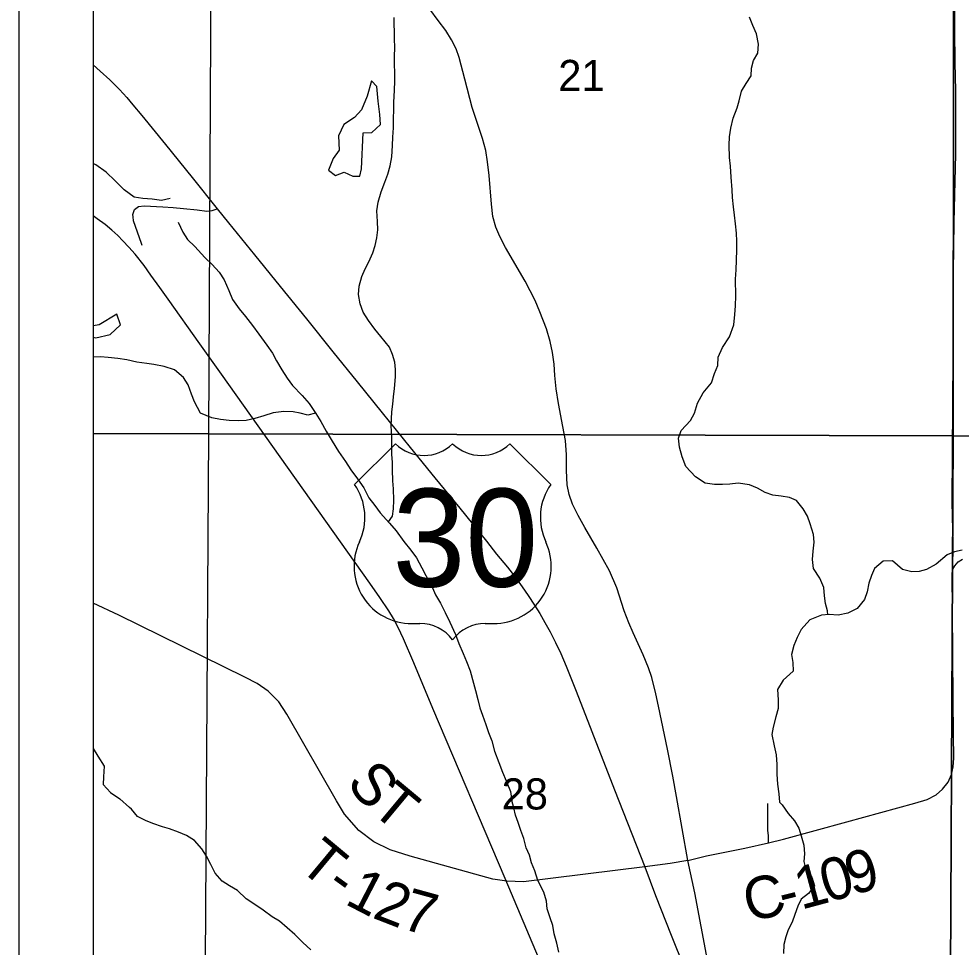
# Model space of a CAD drawing. Extents: x 0 to 34, y 0 to 22.
# Drawn here: x 2 to 3.267, y 18.298 to 19.546 of the extents above; entities that cross this region are included whole.
import ezdxf

# ---------------------------------------------------------------- set-up
doc = ezdxf.new("R2010")
doc.units = 0
for name, color, linetype in [('Default', 7, 'Continuous'), ('SH_Cut_Line', 7, 'Continuous'), ('SH_Data', 7, 'Continuous')]:
    doc.layers.add(name, color=color, linetype=linetype)

msp = doc.modelspace()

# ---------------------------------------------------------------- linework, layer by layer
at = {"layer": 'Default'}
for p, q in [((2.5064, 18.9747), (2.4515, 18.9198)), ((2.7152, 18.9198), (2.6602, 18.9747)), ((2.5284, 18.733), (2.5394, 18.733)), ((2.6273, 18.733), (2.6383, 18.733))]:
    msp.add_line(p, q, dxfattribs=at)
for points in [[(2.1, 20.9), (2.1, 17.0156)], [(3.2565, 19.9852), (3.2557, 19.9639), (3.2561, 19.9392), (3.2581, 19.9016), (3.2594, 19.8699), (3.2596, 19.8254), (3.2589, 19.7384), (3.2581, 19.6526), (3.258, 19.5305), (3.2588, 19.4869), (3.2597, 19.4497), (3.2597, 19.3639), (3.2575, 19.2725), (3.2561, 19.1717), (3.2558, 19.0924), (3.2548, 18.8963), (3.2559, 18.8401), (3.2557, 18.8052)], [(2.8997, 18.4145), (2.8844, 18.5005), (2.8795, 18.5277), (2.8723, 18.5641), (2.8604, 18.6218), (2.8567, 18.6382), (2.8511, 18.6602), (2.8468, 18.6732), (2.8396, 18.691), (2.8259, 18.7204), (2.8202, 18.734), (2.8142, 18.75), (2.8042, 18.781), (2.7941, 18.8036), (2.7774, 18.8343), (2.7611, 18.8621), (2.752, 18.8784), (2.7445, 18.8934), (2.7401, 18.9063), (2.7374, 18.9195), (2.7366, 18.9387), (2.7363, 18.9597), (2.735, 18.979), (2.7317, 18.9978), (2.7255, 19.0289), (2.7224, 19.0487), (2.7207, 19.0666), (2.7198, 19.0818), (2.7177, 19.0976), (2.7147, 19.1124), (2.7097, 19.1293), (2.7007, 19.152), (2.6941, 19.1673), (2.6809, 19.1935), (2.6545, 19.2386), (2.6467, 19.2536), (2.6415, 19.2661), (2.6376, 19.2802), (2.6356, 19.2968), (2.6323, 19.3356), (2.6303, 19.3537), (2.6278, 19.3692), (2.6234, 19.385), (2.6095, 19.4267), (2.5996, 19.465), (2.5919, 19.4941), (2.5881, 19.5059), (2.582, 19.518), (2.5742, 19.5302), (2.5639, 19.5437), (2.5525, 19.5592)], [(2.4971, 18.8696), (2.5026, 18.8771), (2.504, 18.8874), (2.5042, 18.8988), (2.5036, 18.914), (2.5031, 18.925), (2.5025, 18.9394), (2.5023, 18.95), (2.5014, 18.9603), (2.5017, 18.9709), (2.5015, 18.9846), (2.5009, 18.9987), (2.5011, 19.0082), (2.5018, 19.0177), (2.5028, 19.0279), (2.5038, 19.0378), (2.5051, 19.0492), (2.5064, 19.0648), (2.5067, 19.0747), (2.5054, 19.0846), (2.5026, 19.0948), (2.4983, 19.1046), (2.4867, 19.1189), (2.4786, 19.1286), (2.4701, 19.1403), (2.4631, 19.1516), (2.4588, 19.1629), (2.4567, 19.1754), (2.4577, 19.1865), (2.4613, 19.1994), (2.4657, 19.2098), (2.4705, 19.2193), (2.476, 19.2316), (2.4793, 19.2415), (2.4814, 19.2518), (2.4828, 19.2624), (2.4823, 19.2735), (2.4813, 19.2879), (2.483, 19.2997), (2.4874, 19.3134), (2.4921, 19.3264), (2.4962, 19.3371), (2.4994, 19.3485), (2.5015, 19.3607), (2.5025, 19.3756), (2.5031, 19.387), (2.5036, 19.3995), (2.5038, 19.4124), (2.5041, 19.4231), (2.5043, 19.4341), (2.5052, 19.4497), (2.5058, 19.4626), (2.5053, 19.4957), (2.5056, 19.5071), (2.505, 19.5196), (2.5046, 19.5477)], [(3.0879, 18.7448), (3.0876, 18.7502), (3.0848, 18.7601), (3.0835, 18.7703), (3.0826, 18.7813), (3.0771, 18.7938), (3.0686, 18.8069), (3.0673, 18.8191), (3.0683, 18.8301), (3.0696, 18.8423), (3.0687, 18.8525), (3.0643, 18.8669), (3.0604, 18.8775), (3.0546, 18.8873), (3.0457, 18.8982), (3.0362, 18.9026), (3.0252, 18.904), (3.0138, 18.9057), (3.0038, 18.9093), (2.9931, 18.9149), (2.9825, 18.9193), (2.9673, 18.9217), (2.9563, 18.9204), (2.9464, 18.9199), (2.9354, 18.9198), (2.9229, 18.9219), (2.9099, 18.93), (2.8968, 18.9439), (2.8921, 18.9571), (2.8885, 18.97), (2.8872, 18.9821), (2.8908, 18.9925), (2.9031, 19.0059), (2.9087, 19.0159), (2.9127, 19.0292), (2.9204, 19.043), (2.9313, 19.0565), (2.9353, 19.0691), (2.94, 19.0798), (2.9406, 19.0912), (2.9461, 19.1042), (2.9558, 19.1184), (2.9616, 19.1344), (2.963, 19.1485), (2.9639, 19.1603), (2.9641, 19.1736), (2.9638, 19.196), (2.9644, 19.2085), (2.9655, 19.2352), (2.9654, 19.2469), (2.9649, 19.2579), (2.9635, 19.2705), (2.9626, 19.2822), (2.9609, 19.2932), (2.9596, 19.3057), (2.9591, 19.316), (2.9577, 19.3331), (2.9568, 19.3479), (2.9558, 19.3596), (2.9552, 19.3763), (2.9558, 19.3874), (2.9576, 19.3992), (2.9604, 19.4125), (2.9659, 19.4263), (2.9688, 19.4358), (2.9717, 19.4488), (2.978, 19.4591), (2.9847, 19.4695), (2.9853, 19.4797), (2.9878, 19.49), (2.9937, 19.5), (2.9947, 19.5121), (2.9918, 19.5258), (2.9871, 19.5371), (2.9824, 19.5484)], [(2.1, 19.4842), (2.1095, 19.4759), (2.1223, 19.4641), (2.1355, 19.4509), (2.1452, 19.4402), (2.1534, 19.4306), (2.1654, 19.4163), (2.1974, 19.3769), (2.2329, 19.3327), (2.2666, 19.2908), (2.2819, 19.2719), (2.3169, 19.2286), (2.3514, 19.1861), (2.3867, 19.1425), (2.4222, 19.0985), (2.4551, 19.0581), (2.4888, 19.0161), (2.5264, 18.9698), (2.5594, 18.929), (2.5929, 18.8879), (2.6287, 18.8435), (2.6424, 18.8264), (2.657, 18.8086), (2.6677, 18.7948), (2.6768, 18.7825), (2.6851, 18.7708), (2.6935, 18.7577), (2.7006, 18.7463), (2.7074, 18.7345), (2.7143, 18.7219), (2.7218, 18.7075), (2.7287, 18.6927), (2.7359, 18.6758), (2.7494, 18.6419), (2.7705, 18.5876), (2.8011, 18.5093), (2.8418, 18.4057), (2.8563, 18.3674), (2.8772, 18.3138), (2.8945, 18.2702)], [(2.4632, 19.3929), (2.4745, 19.3934), (2.4865, 19.4042), (2.4856, 19.4175), (2.483, 19.4353), (2.4813, 19.455), (2.4743, 19.4625), (2.4685, 19.4419), (2.4608, 19.4236), (2.4515, 19.4136), (2.4372, 19.4039), (2.4299, 19.3886), (2.4309, 19.3696), (2.4227, 19.3581), (2.4165, 19.3424), (2.426, 19.3353), (2.4377, 19.3401), (2.4492, 19.3345), (2.4587, 19.3343), (2.4608, 19.3442)], [(2.4608, 19.3442), (2.4632, 19.3929)], [(2.2033, 19.3047), (2.1918, 19.3016), (2.1792, 19.3037), (2.1667, 19.3047), (2.1549, 19.3064), (2.1415, 19.3161), (2.1296, 19.3281), (2.1173, 19.3397), (2.1035, 19.3497), (2.1, 19.3515)], [(2.1537, 19.2797), (2.1535, 19.2828), (2.1555, 19.2897), (2.1608, 19.2939), (2.1684, 19.2947), (2.1937, 19.2932), (2.2073, 19.2923), (2.2212, 19.2912), (2.2396, 19.2893), (2.2526, 19.2874), (2.2601, 19.2885), (2.2666, 19.2908)], [(2.7985, 18.0482), (2.6541, 18.39), (2.5569, 18.6189), (2.531, 18.6802), (2.5173, 18.7122), (2.51, 18.7277), (2.5037, 18.7397), (2.4975, 18.7499), (2.4854, 18.7679), (2.4718, 18.7871), (2.2725, 19.0682), (2.2434, 19.1091), (2.2008, 19.1691), (2.1894, 19.1846), (2.1777, 19.2012), (2.1685, 19.2143), (2.1563, 19.2297), (2.1481, 19.2392), (2.14, 19.2476), (2.1329, 19.2546), (2.1251, 19.2617), (2.1159, 19.2695), (2.1055, 19.2773), (2.1, 19.281)], [(2.1658, 19.2411), (2.1649, 19.2441), (2.1541, 19.2746), (2.1537, 19.2797)], [(2.2142, 19.2727), (2.2204, 19.2594), (2.227, 19.2493), (2.2366, 19.2399), (2.2501, 19.2253), (2.2601, 19.2159), (2.2693, 19.2054), (2.2763, 19.1949), (2.2826, 19.1806), (2.2873, 19.1688), (2.2962, 19.1561), (2.3047, 19.1459), (2.3143, 19.1335), (2.3225, 19.1219), (2.3337, 19.1072), (2.341, 19.0963), (2.3465, 19.0861), (2.3538, 19.0741), (2.3608, 19.0628), (2.3682, 19.053), (2.3809, 19.0395), (2.3905, 19.029), (2.3994, 19.0154), (2.406, 19.0045), (2.4134, 18.9917), (2.4215, 18.9781), (2.4297, 18.9642), (2.4394, 18.9507), (2.4463, 18.9398), (2.4552, 18.9277), (2.4641, 18.9153), (2.4708, 18.9021), (2.4785, 18.8916), (2.4858, 18.8818), (2.4985, 18.8679), (2.5074, 18.8578), (2.5175, 18.8431), (2.5271, 18.8315), (2.5348, 18.8213), (2.5419, 18.8078), (2.5473, 18.7976), (2.5547, 18.784), (2.5602, 18.7716), (2.5672, 18.7603), (2.5734, 18.7478), (2.5797, 18.735), (2.5871, 18.7184), (2.5918, 18.7059), (2.5977, 18.6927), (2.602, 18.6817), (2.6067, 18.6693), (2.6115, 18.6526), (2.6139, 18.6428), (2.6171, 18.6307), (2.6199, 18.6197), (2.6235, 18.6099), (2.6278, 18.597), (2.6314, 18.5864), (2.6361, 18.5751), (2.6397, 18.5611), (2.6456, 18.546), (2.6503, 18.5331), (2.6554, 18.5214), (2.6612, 18.5071), (2.6629, 18.4951)], [(2.1, 19.1178), (2.1037, 19.1172), (2.1226, 19.1217), (2.1368, 19.1348), (2.1317, 19.1488), (2.108, 19.1347), (2.1, 19.1333)], [(2.3991, 19.0159), (2.3884, 19.013), (2.3785, 19.0159), (2.3687, 19.0177), (2.3565, 19.0182), (2.3421, 19.0161), (2.3293, 19.0122), (2.3172, 19.0086), (2.3055, 19.0061), (2.2953, 19.0056), (2.2827, 19.0058), (2.271, 19.0071), (2.2596, 19.0096), (2.2443, 19.0159), (2.2361, 19.031), (2.2322, 19.0415), (2.2275, 19.054), (2.2216, 19.0638), (2.2094, 19.0739), (2.1956, 19.0786), (2.1816, 19.0811), (2.1721, 19.0825), (2.1588, 19.0846), (2.1451, 19.0874), (2.1333, 19.0895), (2.12, 19.0905), (2.1098, 19.0915), (2.1003, 19.0913), (2.1, 19.0913)], [(3.2685, 18.8318), (3.2583, 18.8294), (3.2485, 18.8251), (3.2335, 18.8127), (3.2207, 18.8057), (3.2105, 18.8029), (3.201, 18.8024), (3.1884, 18.8056), (3.175, 18.8172), (3.1621, 18.817), (3.1505, 18.807), (3.1465, 18.7974), (3.1432, 18.7871), (3.1407, 18.7757), (3.1371, 18.7654), (3.1274, 18.7531), (3.1146, 18.7468), (3.1017, 18.7443), (3.0896, 18.7449), (3.0793, 18.7444), (3.0639, 18.7377), (3.0519, 18.725), (3.0468, 18.7143), (3.042, 18.7036), (3.0391, 18.6914), (3.0408, 18.6804), (3.0413, 18.669), (3.0278, 18.6567), (3.02, 18.6444), (3.021, 18.6304), (3.0212, 18.6186), (3.0179, 18.6075), (3.0143, 18.5938), (3.0126, 18.5839), (3.0158, 18.5687), (3.0186, 18.5566), (3.0192, 18.5433), (3.0194, 18.5304), (3.0203, 18.5168), (3.022, 18.5039), (3.0229, 18.4929)], [(3.2557, 18.8052), (3.2585, 18.8107), (3.2631, 18.816), (3.2692, 18.8197)], [(2.8997, 18.4145), (2.9246, 18.4204), (2.9763, 18.431), (3.0079, 18.4379), (3.0284, 18.4429), (3.1136, 18.4665), (3.2047, 18.4913), (3.2215, 18.4965), (3.2335, 18.5028), (3.2423, 18.5101), (3.2497, 18.5197), (3.2544, 18.5301), (3.2565, 18.5404), (3.2572, 18.5517), (3.257, 18.5838), (3.2564, 18.631), (3.2555, 18.7508), (3.2552, 18.7983), (3.2557, 18.8052)], [(2.8418, 18.4057), (2.6787, 18.3856), (2.6562, 18.3866), (2.6374, 18.3893), (2.5261, 18.4203), (2.4995, 18.4286), (2.4775, 18.4393), (2.4573, 18.4545), (2.438, 18.4767), (2.427, 18.4947), (2.3603, 18.6112), (2.3494, 18.6275), (2.3352, 18.6419), (2.3206, 18.6524), (2.304, 18.6607), (2.1343, 18.744), (2.1, 18.7603)], [(2.1, 18.5651), (2.1063, 18.5546), (2.1148, 18.541), (2.1138, 18.527), (2.1136, 18.5167), (2.1232, 18.5058), (2.1359, 18.4973), (2.1486, 18.4856)], [(2.7263, 18.2912), (2.7235, 18.303), (2.72, 18.3155), (2.7183, 18.3268), (2.7144, 18.337), (2.7105, 18.3495), (2.7096, 18.3594), (2.7061, 18.3718), (2.6979, 18.3873), (2.694, 18.4002), (2.6893, 18.4111), (2.6869, 18.4213), (2.6822, 18.4315), (2.6791, 18.444), (2.6751, 18.4546), (2.6716, 18.4652), (2.6681, 18.4754), (2.6657, 18.4852), (2.6629, 18.4951)], [(3.0079, 18.4379), (3.0082, 18.4477), (3.0073, 18.4547), (3.007, 18.4911)], [(3.0229, 18.4929), (3.0267, 18.489), (3.0344, 18.4777), (3.0429, 18.4675), (3.0487, 18.4577), (3.0522, 18.4475), (3.0558, 18.435), (3.0567, 18.4233), (3.0557, 18.413), (3.0581, 18.4024), (3.0662, 18.3919), (3.0701, 18.3802), (3.0619, 18.3698), (3.0521, 18.3625), (3.0477, 18.353), (3.0433, 18.3416), (3.04, 18.3313), (3.0345, 18.321), (3.0316, 18.3115), (3.0286, 18.3012), (3.0284, 18.2894)], [(2.3925, 18.2942), (2.3817, 18.304), (2.371, 18.3149), (2.3607, 18.3239), (2.3507, 18.3329), (2.3408, 18.3385), (2.3286, 18.3475), (2.3175, 18.3553), (2.3057, 18.3628), (2.2942, 18.374), (2.2835, 18.38), (2.2732, 18.3867), (2.264, 18.3972), (2.2582, 18.4089), (2.2524, 18.4203), (2.2462, 18.4301), (2.2362, 18.4414), (2.2255, 18.4481), (2.2145, 18.4525), (2.2027, 18.4569), (2.1932, 18.4595), (2.1803, 18.4639), (2.1704, 18.468), (2.1594, 18.4736), (2.1513, 18.4833), (2.1486, 18.4856)], [(2.8997, 18.4145), (2.876, 18.4101), (2.8418, 18.4057)], [(2.9478, 18.1631), (2.9423, 18.1959), (2.9345, 18.2352), (2.909, 18.3706), (2.8997, 18.4145)]]:
    msp.add_lwpolyline(points, dxfattribs=at)
for points in [[(2.2603, 19.9741), (3.2572, 19.9844), (3.2565, 18.9852), (2.2553, 18.9881)], [(4.2696, 19.9768), (4.2649, 18.9814), (3.2565, 18.9852), (3.2572, 19.9844)], [(2.1, 19.9754), (2.1, 18.9883), (2.2553, 18.9881), (2.2603, 19.9741)], [(2.1, 18.9883), (2.1, 17.9963), (2.2493, 17.9947), (2.2553, 18.9881)], [(2.2553, 18.9881), (3.2565, 18.9852), (3.2516, 17.9922), (2.2493, 17.9947)], [(3.2565, 18.9852), (4.2649, 18.9814), (4.2617, 17.9979), (3.2516, 17.9922)]]:
    msp.add_lwpolyline(points, close=True, dxfattribs=at)
for centre, radius, start, end in [((2.5449, 19.0139), 0.0549, 225.573, 314.427), ((2.6218, 19.0139), 0.0549, 225.573, 314.427), ((2.3885, 18.8757), 0.0769, 334.5471, 35.0009), ((2.7782, 18.8757), 0.0769, 144.9991, 205.4529), ((2.5276, 18.8099), 0.0769, 154.8319, 270.6383), ((2.6391, 18.8099), 0.0769, 269.3617, 25.1681), ((2.5394, 18.6781), 0.0549, 36.8699, 90), ((2.6273, 18.6781), 0.0549, 90, 143.1301)]:
    msp.add_arc(centre, radius, start, end, dxfattribs=at)
at = {"layer": 'SH_Cut_Line'}
msp.add_lwpolyline([(2.1, 20.9), (2.1, 17.0156)], dxfattribs=at)
at = {"layer": 'SH_Data'}
for p, q in [((2, 21), (2, 14)), ((2.1, 20.9), (2.1, 14.1))]:
    msp.add_line(p, q, dxfattribs=at)

# ---------------------------------------------------------------- texts
at = {"layer": 'Default'}
for s, height, rotation, p in [('21', 0.04186, 0, (2.7254, 19.449)), ('30', 0.000189, 0, (2.5442, 18.8081)), ('S', 0.0568, 310.2302, (2.439, 18.5178)), ('T', 0.0568, 320.1216, (2.4713, 18.481)), ('28', 0.04186, 0, (2.6492, 18.4829)), ('T', 0.0568, 320.2471, (2.374, 18.4049)), ('9', 0.0568, 16.3395, (3.1207, 18.3671)), ('0', 0.0568, 16.045, (3.0867, 18.3573)), ('1', 0.0568, 15.0793, (3.0519, 18.3479)), ('-', 0.0568, 324.0809, (2.4099, 18.3752)), ('1', 0.0568, 332.6279, (2.4367, 18.3567)), ('C', 0.0568, 12.815, (2.9814, 18.3313)), ('2', 0.0568, 338.7663, (2.4738, 18.3378)), ('7', 0.0568, 344.5853, (2.5124, 18.3232)), ('-', 0.0568, 14.1507, (3.0283, 18.342))]:
    msp.add_text(s, height=height, rotation=rotation, dxfattribs=at).set_placement(p)
for s, height, p in [('30', 0.13184, (2.5024, 18.7824)), ('0', 0.000189, (2.5833, 18.8473)), ('/', 0.000189, (2.5833, 18.8473))]:
    msp.add_text(s, height=height, dxfattribs=at).set_placement(p)

doc.saveas('drawing.dxf')
